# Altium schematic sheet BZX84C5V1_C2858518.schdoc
size 127 x 101 mm
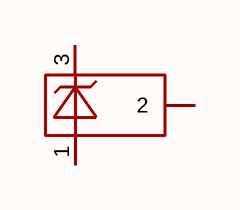
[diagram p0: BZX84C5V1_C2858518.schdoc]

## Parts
D?  bzx84c5v1  [SOT-23-3_L2.9-W1.5-P1.90-LS2.6-BL]  (value not drawn)

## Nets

Not connected (* = marked no-connect by the designer): D? 1(3) 2 3

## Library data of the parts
D? = bzx84c5v1: 二极管配置:1个独立式;稳压值(标称值):5.1V;稳压值(范围):4.8V~5.4V;耗散功率(Pd):300mW;; Manufacturer: MDD(辰达半导体); Symbol: BZX84C5V1_C2858518; AddInBom: yes; ModelId: ff0338e7aed74aa5b635b30fa099325e; ModelTransform: 114.173,100.394,0,0,0,0,0,0,0; Diode Configuration: 1个独立式; Zener Voltage(Nom): 5.1V; Reverse Leakage Current (Ir): 2uA@2V; Pd - Power Dissipation: 300mW; Impedance(Zzt): 60Ω; Impedance(Zzk): 480Ω; Operating Junction Temperature Range: -55℃~+150℃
